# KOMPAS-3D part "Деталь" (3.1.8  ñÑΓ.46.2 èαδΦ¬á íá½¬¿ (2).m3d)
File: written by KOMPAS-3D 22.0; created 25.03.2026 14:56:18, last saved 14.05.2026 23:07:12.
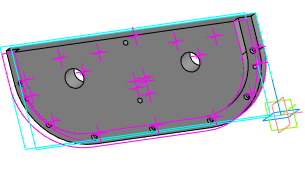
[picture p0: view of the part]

Document properties: Автор: TMK; Полное имя файла: E:\test_kompas\all_v20\3.1.8  дет.46.2 Крышка балки (2).m3d; Организация: TMK

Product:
- Part/product: Деталь
    Масса: 21.934157

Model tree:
1. Операция без истории:1
2. Эскиз:1
3. Смещенная плоскость:1  (with: Операция без истории:1)
4. Эскиз:2
5. Смещенная плоскость:2  (with: Операция без истории:1)
6. Эскиз:3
